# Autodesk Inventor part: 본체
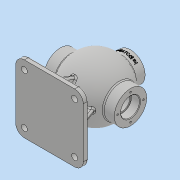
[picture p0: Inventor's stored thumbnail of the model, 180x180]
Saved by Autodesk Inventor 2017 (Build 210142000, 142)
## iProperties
Part Number: 본체
Material: 일반
Document SubType Name: Modeling
Designer: MRC
Density: 1 g/cm^3
Appearance: 기본값
Author: MRC
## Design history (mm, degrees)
sketch "스케치1"
  geometry: L1 (-65, 0)-(65, 0); L2 (-65, 0)-(-65, 30); L3 (-65, 30)-(-44.9, 30); L4 (65, 0)-(65, 30); L5 (65, 30)-(44.9, 30); A1 r 54 centre (0, 0) between (54, 0) and (-54, 0); A2 r 44 centre (0, 0) between (44, 0) and (-44, 0); 2 further points
  constraints: 10 end point, 6 point on circle, 6 point on line, 3 coincident, 2 centre point, 2 perpendicular, 1 horizontal, 1 midpoint, 1 vertical
  dimensions: "d0" = 130 distance of L1.start L1.end; "d1" = 108 diameter of A1; "d3" = 88 diameter of A2; "d15" = 60 diameter of L5 L1
node "작업 평면2"
sketch "스케치3"
  geometry: L1 (62.5, 62.5)-(-62.5, 62.5); L2 (-62.5, 62.5)-(-62.5, -62.5); L3 (-62.5, -62.5)-(62.5, -62.5); L4 (62.5, -62.5)-(62.5, 62.5); L5 (62.5, 62.5)-(-62.5, -62.5); L6 (-62.5, 62.5)-(62.5, -62.5); 1 further point
  constraints: 12 end point, 2 midpoint, 2 parallel, 1 horizontal, 1 perpendicular
  dimensions: "d10" = 125 distance of L3.end L2.end; "d11" = 125 distance of L2.end L1.end
extrude "돌출1" join sketch "스케치3" distance "d12" = 10; taper "d13" = 0 deg
revolve "회전2" stored, may be unused: angle "d16" = 90 deg
node "작업 평면3"
sketch "스케치4"
  geometry: C1 r 27 at (0, 0); 1 further point
  constraints: 1 centre point, 1 coincident
  dimensions: "d18" = 54 diameter of C1
extrude "돌출2" join sketch "스케치4" stored distance "d19" = 10; taper "d20" = 0 deg
sketch "스케치5"
  geometry: C1 r 30 at (0, 0) reference; C2 r 17.5 at (0, 0)
  constraints: 1 centre point, 1 coincident
  dimensions: "d21" = 35 diameter of C2
extrude "돌출3" cut sketch "스케치5" distance "d22" = 16; taper "d23" = 0 deg
sketch "스케치6"
  geometry: C1 r 30 at (0, 0) reference; C2 r 15 at (0, 0)
  constraints: 1 centre point, 1 coincident
  dimensions: "d24" = 30 diameter of C2
extrude "돌출4" cut sketch "스케치6" stored distance "d25" = 16; taper "d26" = 0 deg
sketch "스케치7"
  geometry: L1 (0, 0)-(0, 24); C1 r 30 at (0, 0) reference; 1 further point
  constraints: 2 end point, 1 coincident, 1 vertical
  dimensions: "d27" = 24 distance of L1.start L1.end
hole "구멍1" sketch "스케치7" at (0, 24) diameter "d28" = 3.242; stored, may be unused: countersink angle "d32" = 90 deg, drill point angle "d34" = 118 deg; dims "d29" = 12, "d30" = 4, "d31" = 2, "d33" = 15
chamfer "모따기1" distance "d38" = 1; stored, may be unused: second distance "d39" = 2, angle "d40" = 45 deg
fillet "모깎기1" dims "d41" = 0.6
sketch "스케치8"
  geometry: C1 r 27 at (0, 0) reference; C2 r 13 at (0, 0)
  constraints: 1 centre point, 1 coincident
  dimensions: "d42" = 26 diameter of C2
extrude "돌출5" cut sketch "스케치8" stored distance "d43" = 16; taper "d44" = 0 deg
chamfer "모따기2" distance "d45" = 1; stored, may be unused: second distance "d46" = 2, angle "d47" = 45 deg
sketch "스케치9"
  geometry: L1 (0, 0)-(0, 20); C1 r 14 at (0, 0) reference; 1 further point
  constraints: 2 end point, 1 coincident, 1 vertical
  dimensions: "d48" = 20 distance of L1.start L1.end
hole "구멍2" sketch "스케치9" at (0, 20) diameter "d49" = 3.242; stored, may be unused: countersink angle "d53" = 90 deg, drill point angle "d55" = 118 deg; dims "d50" = 9, "d51" = 4, "d52" = 2, "d54" = 11
fillet "모깎기4" dims "d73" = 16
sketch "스케치12"
  geometry: C1 r 5.5 at (46.5, -46.5); C2 r 5.5 at (-46.5, -46.5); C3 r 5.5 at (46.5, 46.5); C4 r 5.5 at (-46.5, 46.5); A1 r 16 centre (46.5, 46.5) between (62.5, 46.5) and (46.5, 62.5) reference; A2 r 16 centre (-46.5, 46.5) between (-46.5, 62.5) and (-62.5, 46.5) reference; A3 r 16 centre (-46.5, -46.5) between (-62.5, -46.5) and (-46.5, -62.5) reference; A4 r 16 centre (46.5, -46.5) between (46.5, -62.5) and (62.5, -46.5) reference; 1 further point
  constraints: 4 centre point, 4 coincident
  dimensions: "d74" = 11 diameter of C1; "d75" = 11 diameter of C2; "d76" = 11 diameter of C3; "d77" = 11 diameter of C4
extrude "돌출8" cut sketch "스케치12" stored distance "d78" = 8; taper "d79" = 0 deg
fillet "모깎기5" dims "d80" = 3
fillet "모깎기6" dims "d81" = 3
fillet "모깎기7" dims "d82" = 3
sketch "스케치13"
  geometry: L1 (-50.5, 4)-(50.5, 4); L2 (50.5, 4)-(50.5, -4); L3 (50.5, -4)-(-50.5, -4); L4 (-50.5, -4)-(-50.5, 4); L5 (-50.5, 4)-(50.5, -4); L6 (50.5, 4)-(-50.5, -4); L7 (4, 50.5)-(-4, 50.5); L8 (-4, 50.5)-(-4, -50.5); L9 (-4, -50.5)-(4, -50.5); L10 (4, -50.5)-(4, 50.5); L11 (4, 50.5)-(-4, -50.5); L12 (-4, 50.5)-(4, -50.5); 1 further point
  constraints: 24 end point, 4 midpoint, 4 parallel, 2 horizontal, 2 perpendicular
  dimensions: "d83" = 8 distance of L1.end L2.end; "d84" = 8 distance of L8.end L9.end; "d85" = 101 distance of L2.end L3.end; "d86" = 101 distance of L9.end L7.start
extrude "돌출9" join sketch "스케치13" stored distance "d87" = 8; taper "d88" = 0 deg
feature "면 기울기1" dims angle "d89" = 20 deg
fillet "모깎기8" dims "d90" = 3
fillet "모깎기9" dims "d91" = 3
node "작업 평면4"
sketch "스케치14"
  geometry: L1 (-27, 65)-(27, 65) reference; 2 further points
  constraints: 1 vertical alignment, 1 other
  dimensions: "d93" = 9 distance from line of L1 point (0, 56)
feature "엠보싱1" sketch "스케치14" dims "d0" = 130, "d1" = 108, "d3" = 88, "d15" = 60, "d94" = 0.5, "d95" = 0
chamfer "모따기3" distance "d102" = 1; stored, may be unused: second distance "d103" = 2, angle "d104" = 45 deg
fillet "모깎기10" dims "d105" = 0.6
node "솔리드1"
pattern_circular "원형 패턴3" dims angle "d97" = 360 deg
pattern_circular "원형 패턴4" dims angle "d100" = 360 deg
mirror "미러2"
mirror "미러3"
other parameters: "d9" = -85, "d17" = 65, "d92" = 131.5
